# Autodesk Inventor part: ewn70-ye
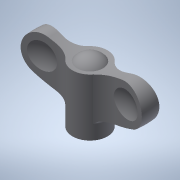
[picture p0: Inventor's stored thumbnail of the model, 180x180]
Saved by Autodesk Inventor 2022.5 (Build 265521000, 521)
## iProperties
Created: 2016-12
Part Number: ewn70-ye
Material: 一般
Document SubType Name: Modeling
Designer: imaocorp
Density: 1 g/cm^3
Appearance: 既定
Author: imaocorp
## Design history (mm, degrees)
node "ewn70-ye.x_t1"
node "ewn70-ye"
node "Base1"
